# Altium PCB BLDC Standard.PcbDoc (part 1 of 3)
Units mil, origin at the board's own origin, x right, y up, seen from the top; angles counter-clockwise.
Board outline 4950 x 3000 mil, 4 copper layers (Top Layer, MidLayer1, MidLayer2, Bottom Layer), stack 63.4 mil thick; 211 components, 117 nets, 576 pads, 1027 vias.
Unrouted connection lines stored in the file: 2.
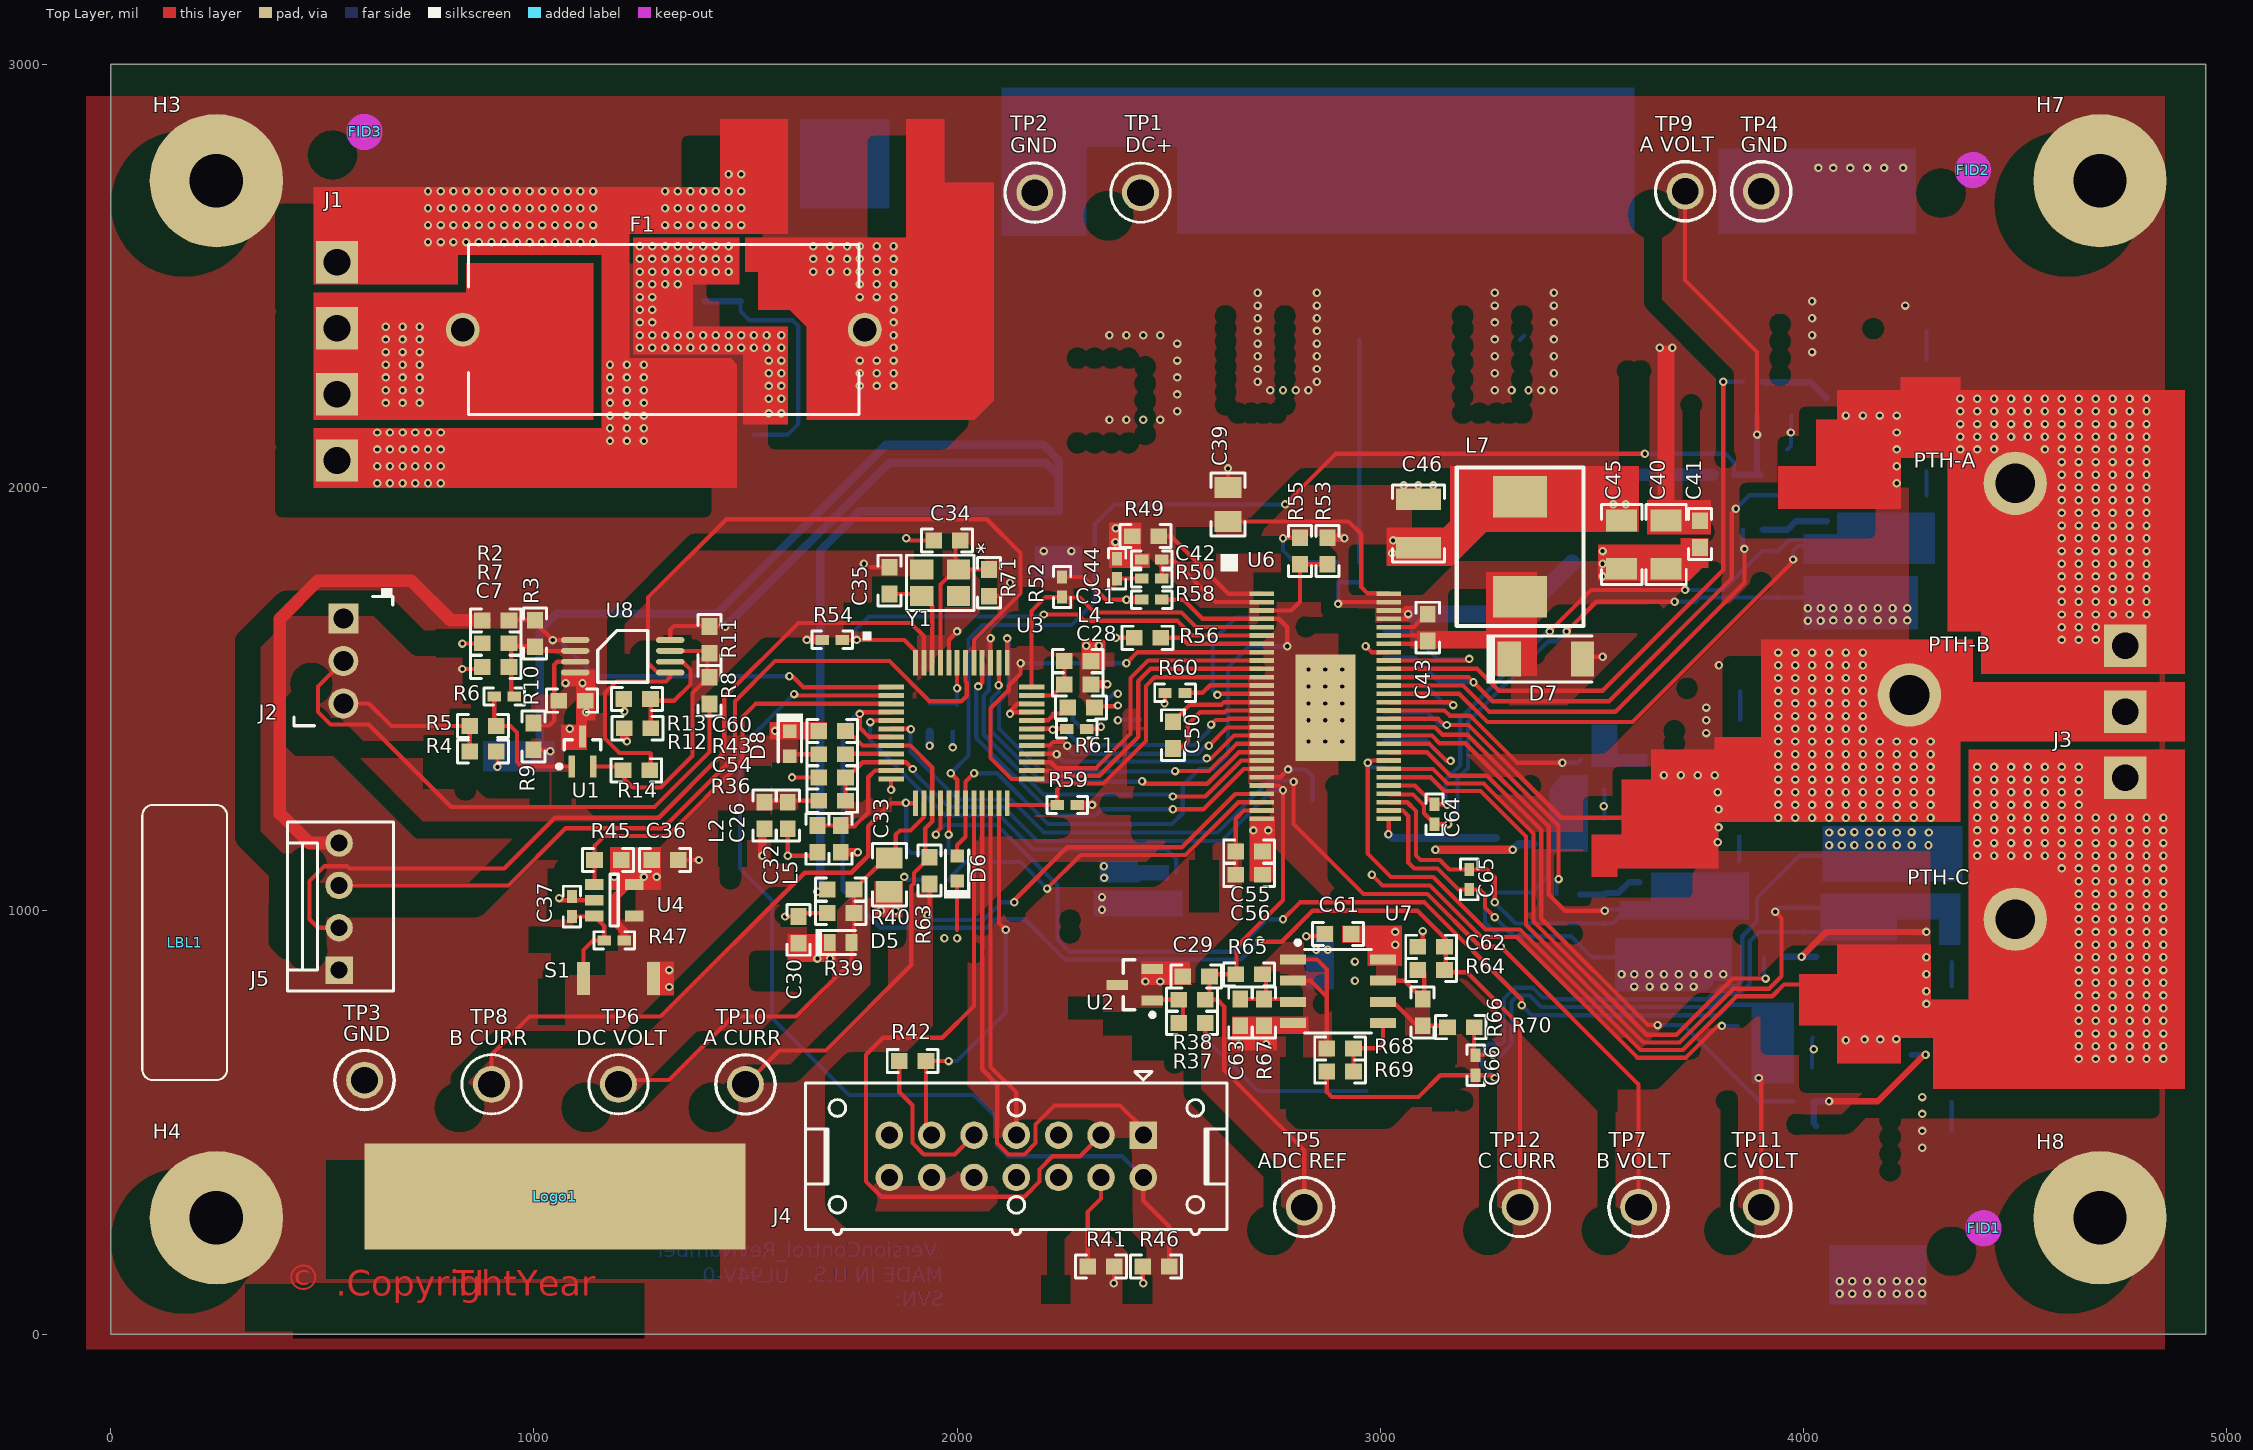
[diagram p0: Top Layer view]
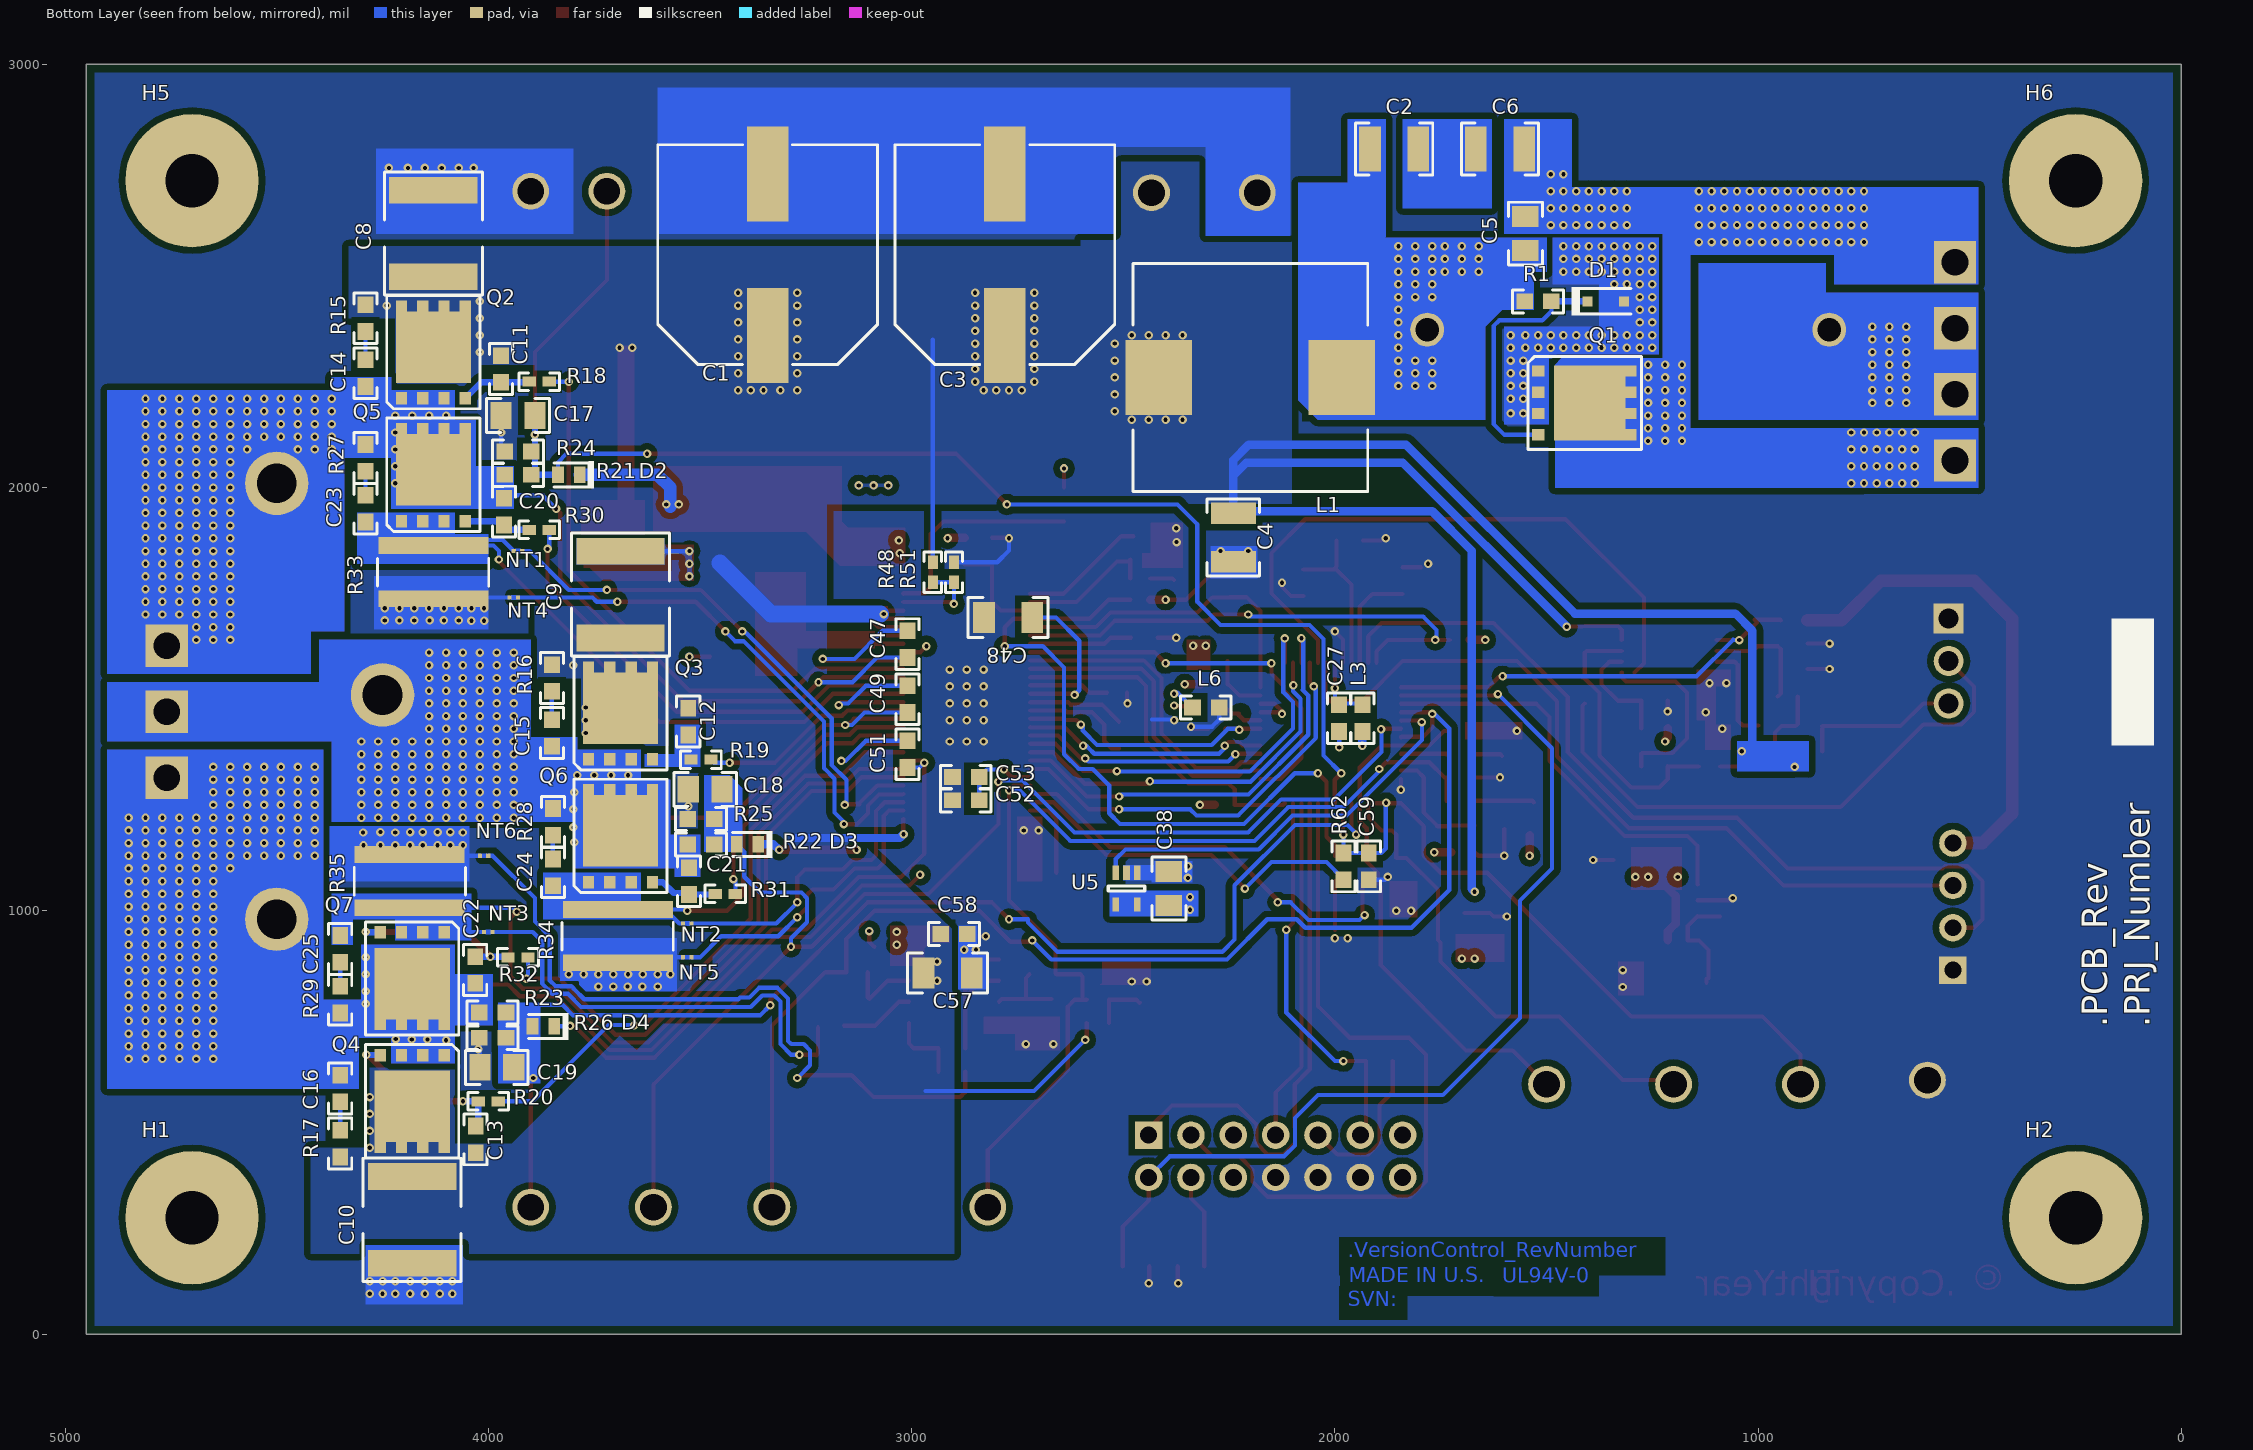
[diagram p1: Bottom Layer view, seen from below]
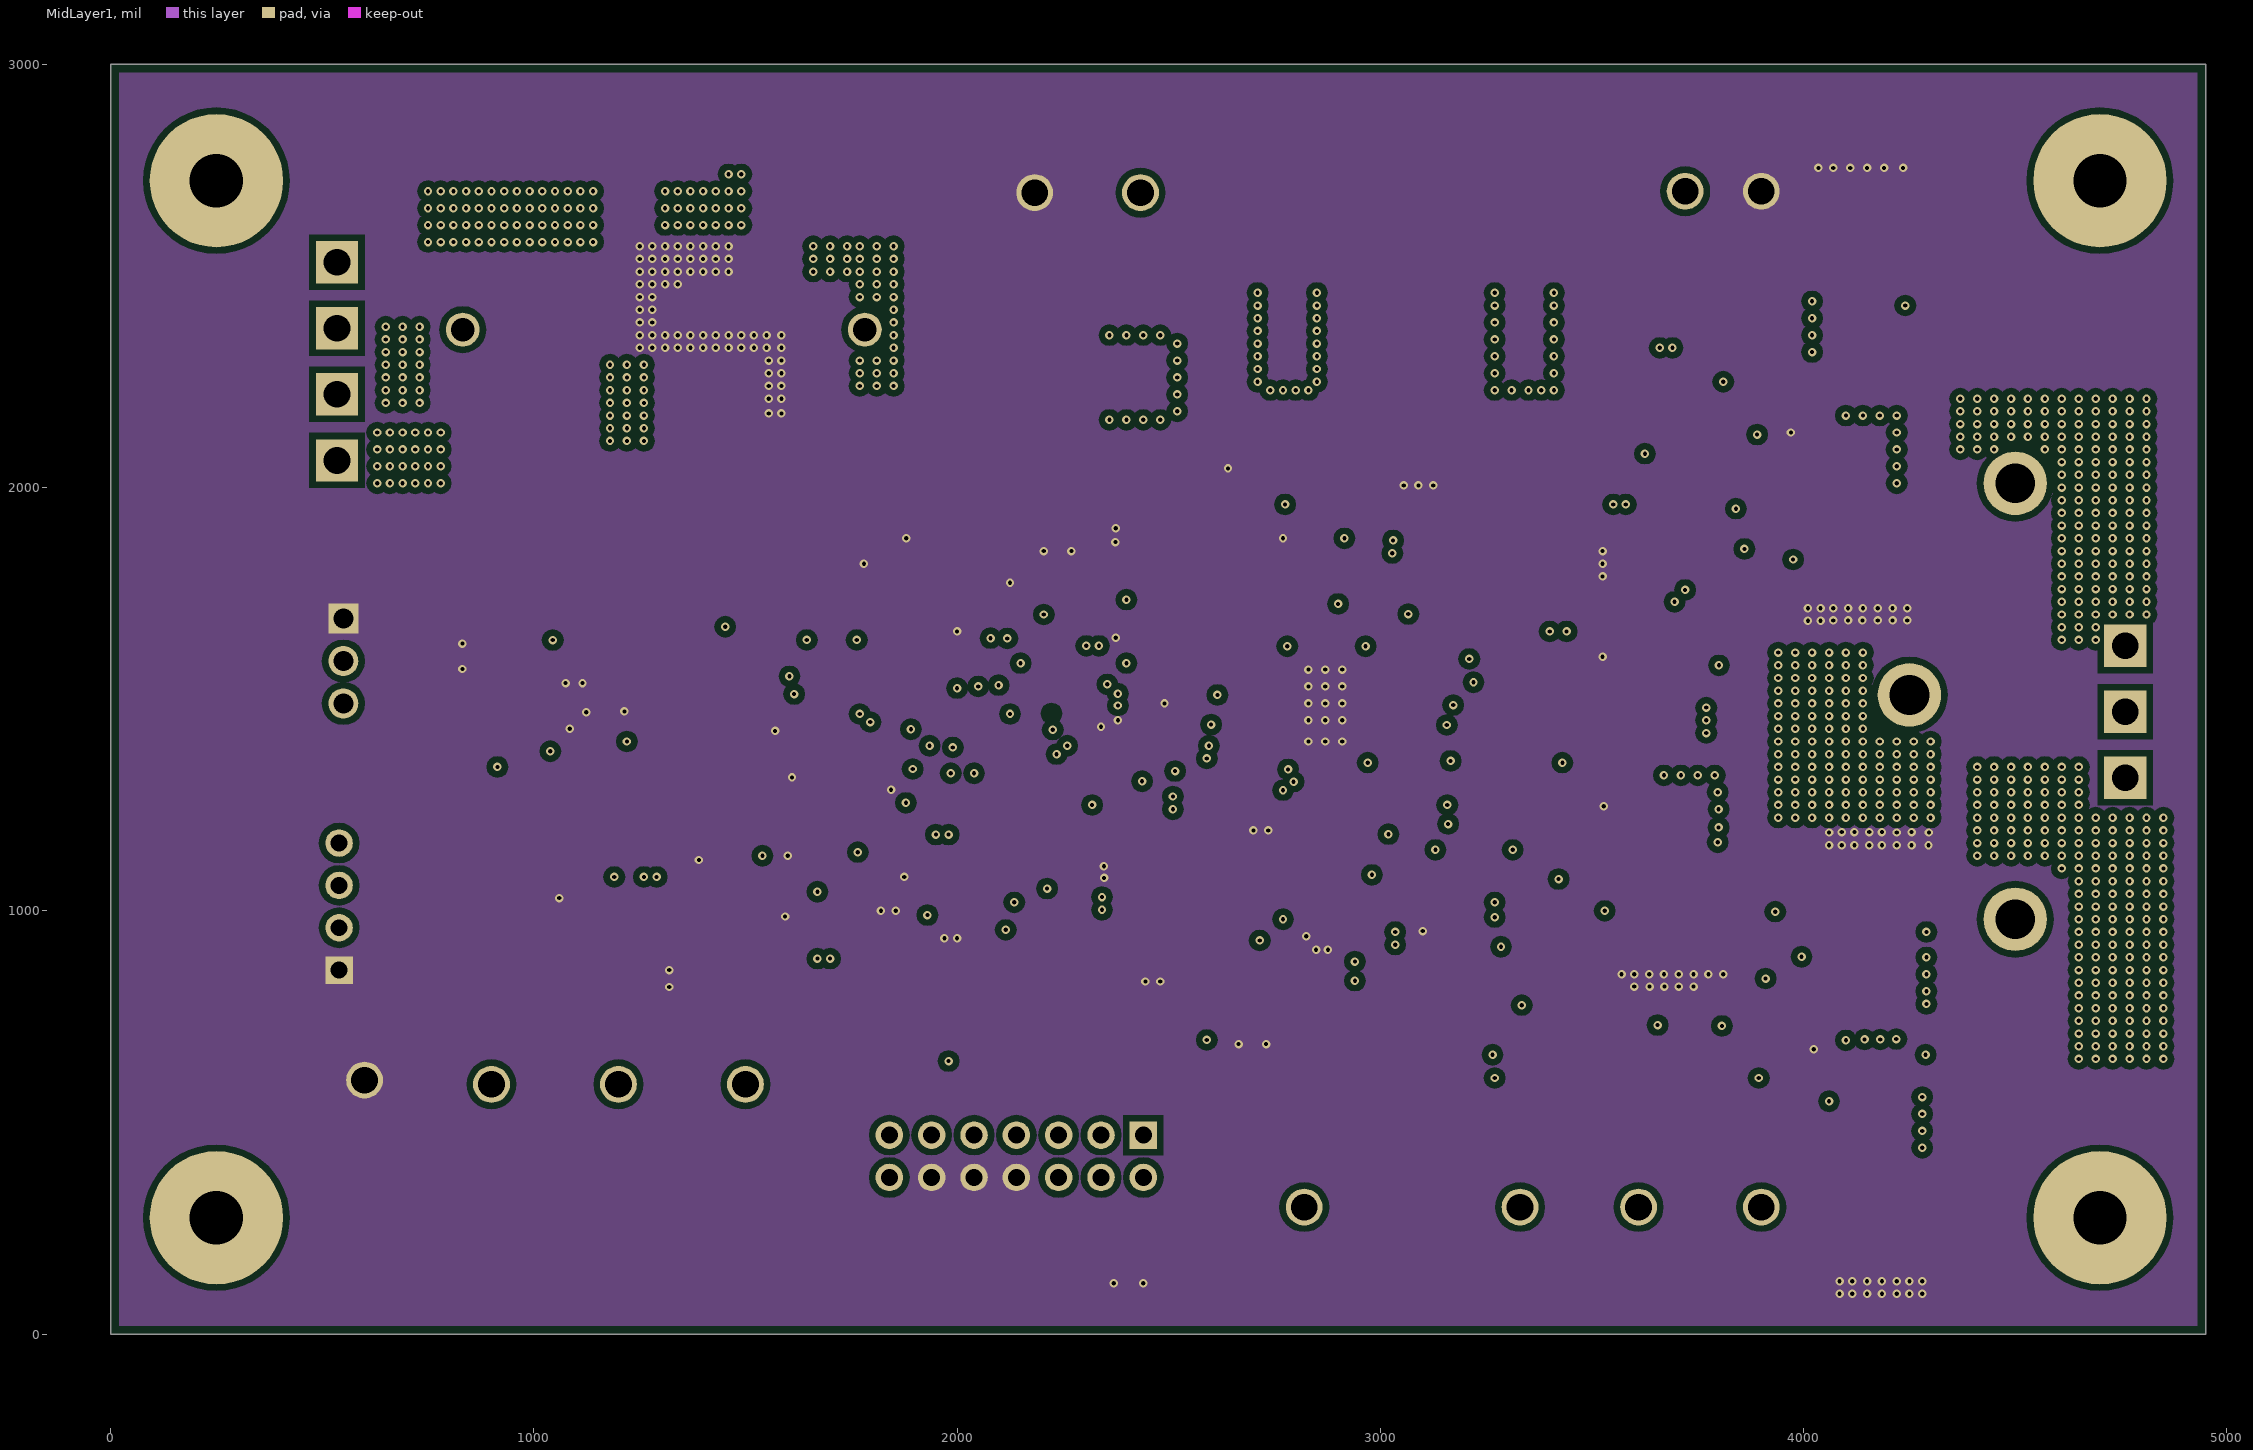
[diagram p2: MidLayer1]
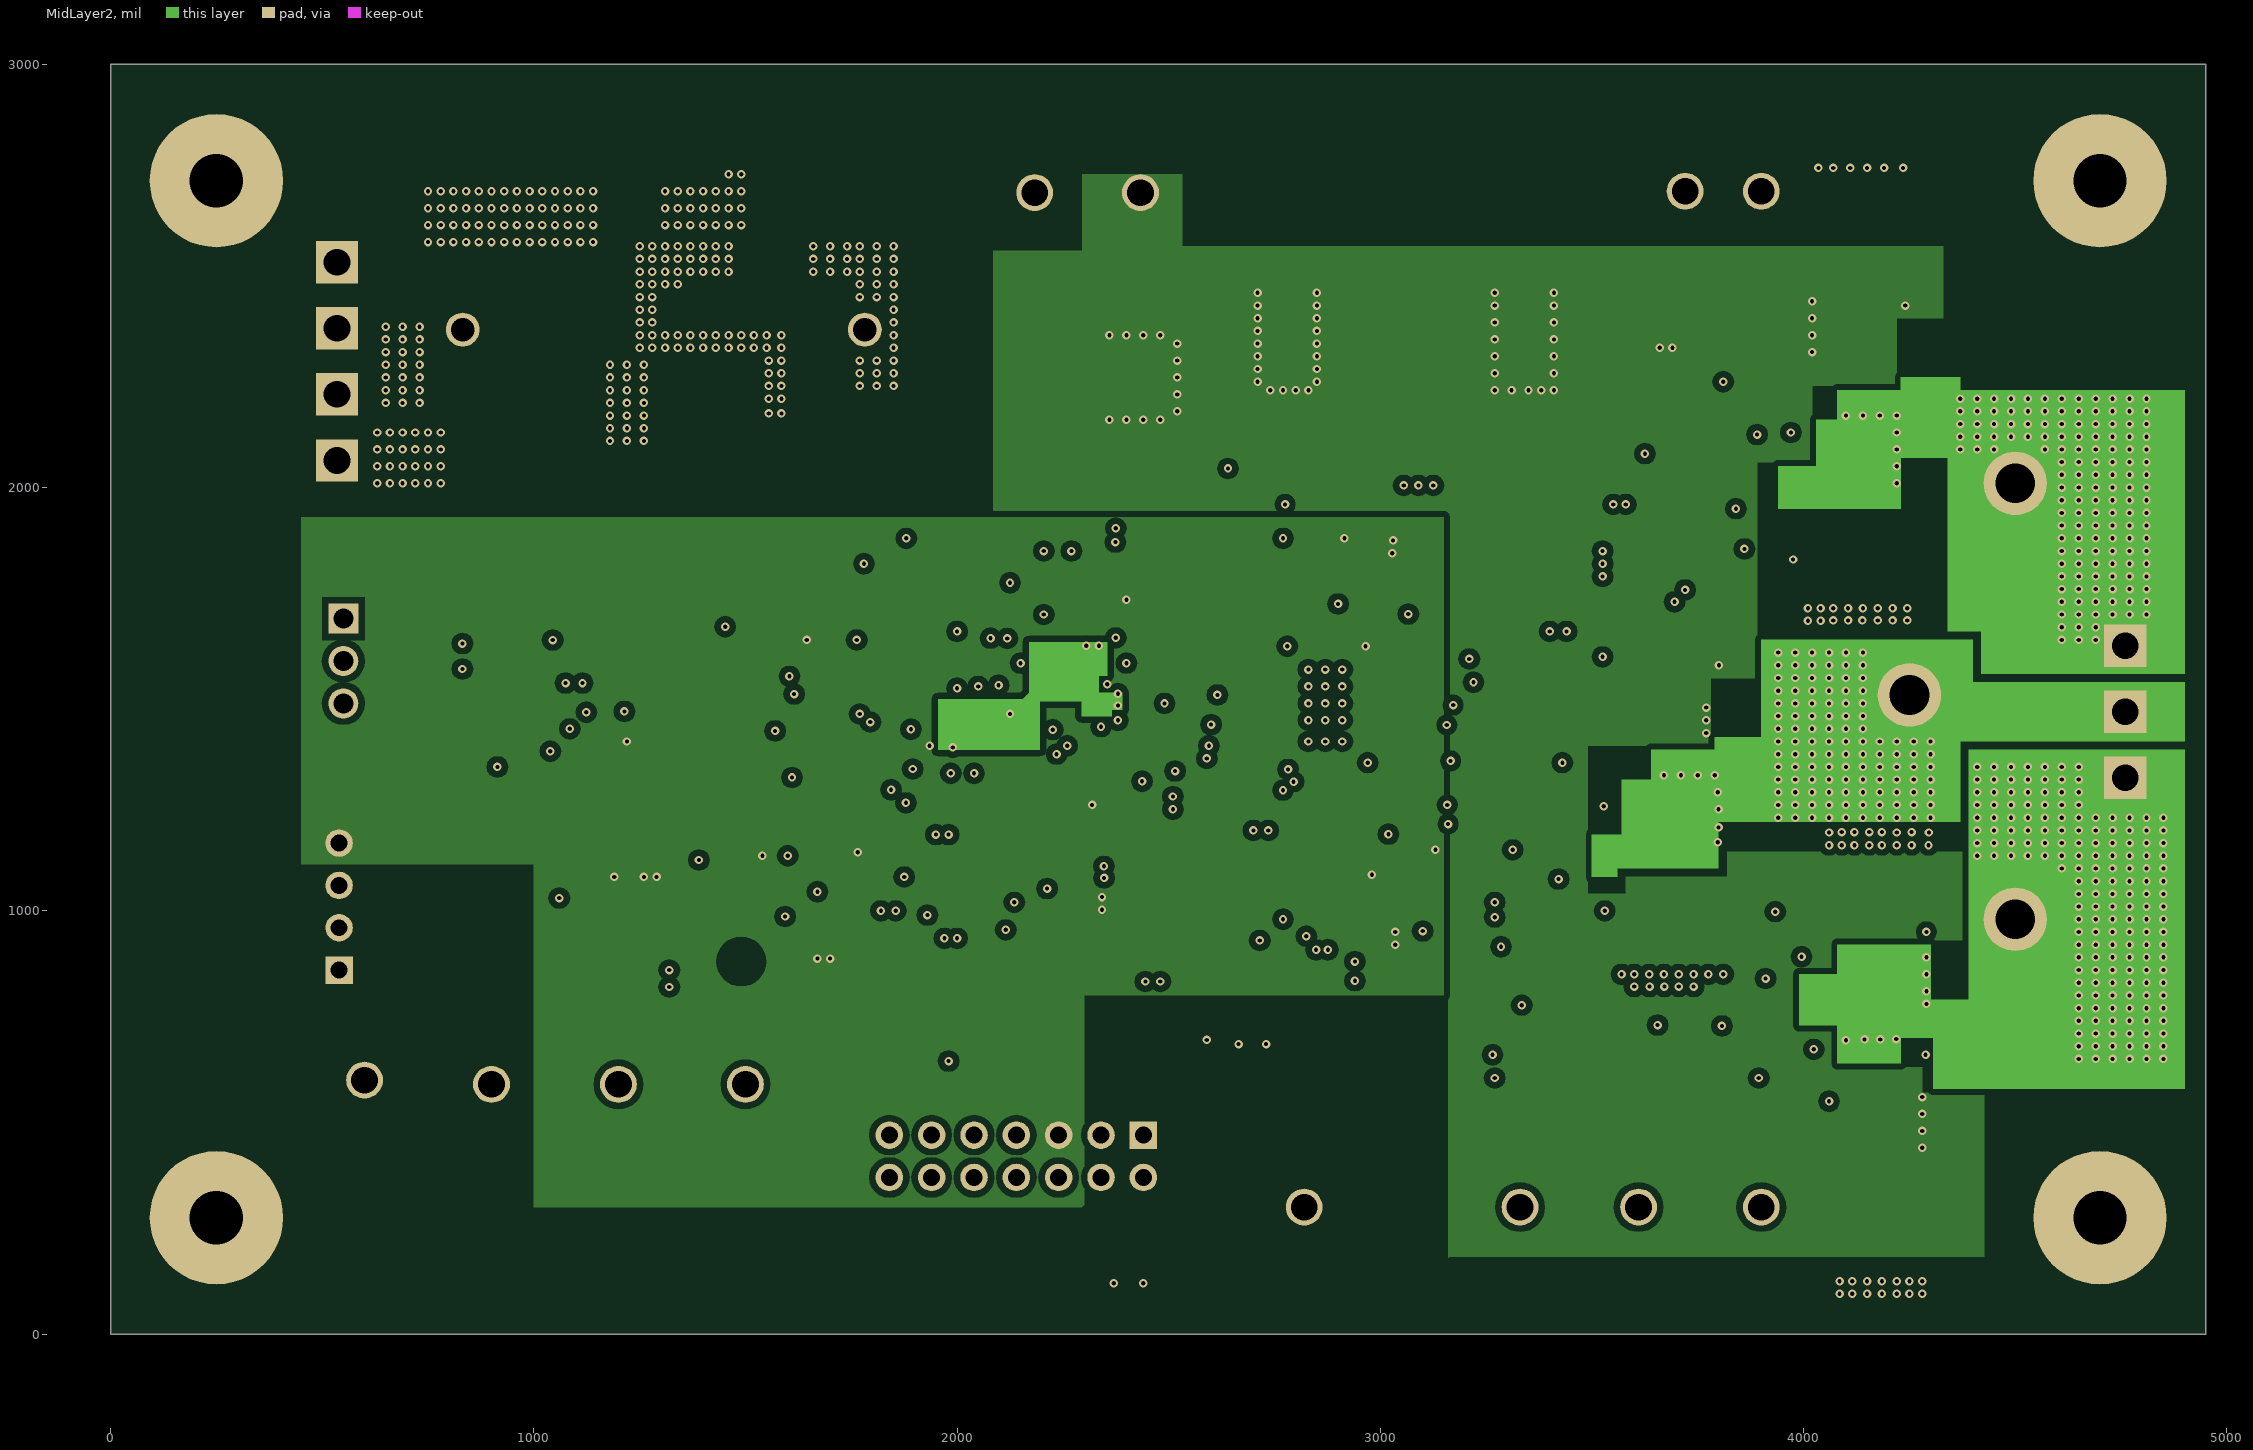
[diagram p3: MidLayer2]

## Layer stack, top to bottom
Top Layer: signal copper 1.4
Dielectric: prepreg 12.6, 370HR, Dk 4.8
MidLayer1: signal copper 1.4
Dielectric: core 32.6, 370HR, Dk 4.8
MidLayer2: signal copper 1.4
Dielectric: prepreg 12.6, 370HR, Dk 4.8
Bottom Layer: signal copper 1.4

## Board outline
0,0 4950,0 4950,3000 0,3000

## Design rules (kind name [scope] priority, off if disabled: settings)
AcuteAngle [All] p1: minimum=4.50000000000000E+0001 checktracksonly=FALSE
AssemblyTestPointUsage [All] p1: valid=2
Clearance Clearance_1 [InComponent('U3')] p1: gap=4
Clearance Clearance_BoardEdge_MountingHoles [OnCopper and InComponentClass('Mounting Holes') vs IsKeepOut] p2: gap=40
Clearance Clearance_BoardEdge_Poly [OnCopper and InPoly vs IsKeepOut] p3: gap=15
Clearance Clearance_BoardEdge [OnCopper and Not InComponentClass('Logo') and not InComponentClass('FiducialMark') and not InRegion(1000,500,4000,800) and Not IsKeepout vs IsKeepOut] p4: gap=75
Clearance Clearance_Poly [InPolygon] p5: gap=15
Clearance [All] p6: gap=8
ComponentClearance ComponentClearance_Logo [InComponentClass('Logo')] p1 off: gap=50 collisioncheckmode=3 verticalgap=10 showdistances=FALSE
ComponentClearance ComponentClearance_ScrewToNut [(HasFootprint('NY PMS 440 0025 PH')) vs (HasFootprint('Keystone_1902C'))] p2: gap=5 collisioncheckmode=3 verticalgap=10 showdistances=FALSE
ComponentClearance ComponentClearance_MountingHoles [InComponentClass('Mounting Holes')] p3 off: gap=250 collisioncheckmode=3 verticalgap=100000 showdistances=FALSE
ComponentClearance ComponentClearance_SmallPassives [HasFootprint('0201*') or HasFootprint('0402*') or HasFootprint('0508') or HasFootprint('0603*') or HasFootprint('0612') or HasFootprint('0805*') or HasFootprint('0815*') or HasFootprint('0830*') or HasFootprint('1206*') or HasFootprint('1210*') or HasFootprint('1808*') or HasFootprint('1812*') or HasFootprint('1825*') or HasFootprint('2010*') or HasFootprint('2220*') or HasFootprint('2225*') or HasFootprint('2512*') or HasFootprint('2728*') or HasFootprint('3518*') vs HasFootprint('0201*') or HasFootprint('0402*') or HasFootprint('0508') or HasFootprint('0603*') or HasFootprint('0612') or HasFootprint('0805*') or HasFootprint('0815*') or HasFootprint('0830*') or HasFootprint('1206*') or HasFootprint('1210*') or HasFootprint('1808*') or HasFootprint('1812*') or HasFootprint('1825*') or HasFootprint('2010*') or HasFootprint('2220*') or HasFootprint('2225*') or HasFootprint('2512*') or HasFootprint('2728*') or HasFootprint('3518*')] p4: gap=5 collisioncheckmode=3 verticalgap=10 showdistances=FALSE
ComponentClearance ComponentClearance_THtoSMT [IsThruComponent vs IsSMTComponent] p5: gap=20 collisioncheckmode=3 verticalgap=30 showdistances=FALSE
ComponentClearance ComponentClearance_THtoTH [IsThruComponent vs IsThruComponent] p6: gap=20 collisioncheckmode=3 verticalgap=30 showdistances=FALSE
ComponentClearance [All] p7 off: gap=40 collisioncheckmode=3 verticalgap=10 showdistances=FALSE
DiffPairsRouting [All] p1: maxlimit=100 minlimit=10 mostfreqgap=10 maxuncoupledlength=1000
FabricationTestPointUsage TestPointUsage [All] p1: valid=2 allowmultiple=FALSE
FabricationTestpoint Testpoint [All] p1: side=3 testpointundercomponent=TRUE minsize=40 maxsize=100 preferedsize=60 minholesize=0 maxholesize=40 preferedholesize=32 testpointgrid=1 allowsidetop=TRUE allowsidebottom=TRUE usegrid=TRUE gridtolerance=0.01
FanoutControl Fanout_LCC [IsLCC] p1: bgadir=Out bgaviamode=Centered fanoutstyle=Auto fanoutdirection=Alternating viagrid=1 // Fanout_LCC (Default Rule)
FanoutControl Fanout_BGA [IsBGA] p2: bgadir=Out bgaviamode=Centered fanoutstyle=Auto fanoutdirection=Alternating viagrid=1 // Fanout_BGA (Default Rule)
FanoutControl Fanout_Default [All] p4: bgadir=Out bgaviamode=Centered fanoutstyle=Auto fanoutdirection=Alternating viagrid=1 // Fanout_Default (Default Rule)
FanoutControl Fanout_Small [(CompPinCount < 5)] p5: bgadir=Out bgaviamode=Centered fanoutstyle=Auto fanoutdirection=OutThenIn viagrid=1 // Fanout_Small (Default Rule)
HoleSize [All] p1: absolutevalues=TRUE maxlimit=251 minlimit=8 maxpercent=80.000 minpercent=20.000
MinimumAnnularRing MinimumAnnularRing_ThermalPadVias [IsVia and InAnyComponent] p1: minimumring=5
MinimumAnnularRing [All] p2: minimumring=5
MinimumSolderMaskSliver MinimumSolderMaskSliver_Logo [InComponentClass('Logo') vs InComponentClass('Logo')] p1: minsoldermaskwidth=0.7
MinimumSolderMaskSliver [All] p2: minsoldermaskwidth=2.5
PlaneClearance [All] p1: clearance=5
PlaneConnect [All] p1: planeconnectstyle=Direct reliefexpansion=10 reliefentries=4 reliefconductorwidth=10 reliefairgap=10
PolygonConnect [All] p1: connectstyle=Direct reliefconductorwidth=10 reliefentries=4 polygonreliefangle="90 Angle" airgapwidth=10
RoomDefinition Hardware_ANSI-B [InComponentClass('Hardware_ANSI-B')] p1: confinementstyle=ConfineIn formatcopy=TRUE lockcomponents=FALSE outline -692,-1534 1308,-1534 1308,-534 -692,-534
RoomDefinition "BLDC Standard sheet 4" [InComponentClass('BLDC Standard sheet 4')] p2: confinementstyle=ConfineIn formatcopy=TRUE lockcomponents=FALSE outline -692,-1534 1308,-1534 1308,-534 -692,-534
RoomDefinition "BLDC Standard sheet 3" [InComponentClass('BLDC Standard sheet 3')] p3: confinementstyle=ConfineIn formatcopy=TRUE lockcomponents=FALSE outline -692,-1534 1308,-1534 1308,-534 -692,-534
RoomDefinition "BLDC Standard sheet 2" [InComponentClass('BLDC Standard sheet 2')] p4: confinementstyle=ConfineIn formatcopy=TRUE lockcomponents=FALSE outline -692,-1534 1308,-1534 1308,-534 -692,-534
RoomDefinition "BLDC Standard sheet 1" [InComponentClass('BLDC Standard sheet 1')] p5: confinementstyle=ConfineIn formatcopy=TRUE lockcomponents=FALSE outline -692,-1534 1308,-1534 1308,-534 -692,-534
RoutingVias ThermalPadVias [IsVia and InAnyComponent] p1: holewidth=7.87 width=19.68 viastyle="Through Hole" minholewidth=7.87 minwidth=19.68 maxholewidth=12.99 maxwidth=23.62
RoutingVias [All] p2: holewidth=16 width=34 viastyle="Through Hole" minholewidth=7.87 minwidth=20 maxholewidth=40 maxwidth=65
SMDToCorner [All] p1: distance=30000
SilkToSilkClearance [All] p1: silktosilkclearance=3
SilkscreenOverComponentPads [All] p1: minsilkscreentomaskgap=3
SolderMaskExpansion [All] p1: expansion=1.97
Width [All] p1: maxlimit=100 minlimit=6 preferedwidth=10 checkconnectedcopper=TRUE
13 further rules are at their usual default settings.

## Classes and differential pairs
component class "BLDC Standard sheet 4": C8 C9 C10 C11 C12 C13 C14 C15 C16 C17 C18 C19 C20 C21 C22 C23 C24 C25 D2 D3 D4 J3 NT1 NT2 NT3 NT4 NT5 NT6 PTH-A PTH-B PTH-C Q2 Q3 Q4 Q5 Q6 Q7 R15 R16 R17 R18 R19 R20 R21 R22 R23 R24 R25 R26 R27 R28 R29 R30 R31 R32 R33 R34 R35
component class "BLDC Standard sheet 3": C39 C40 C41 C42 C43 C44 C45 C46 C47 C48 C49 C50 C51 C52 C53 C54 C55 C56 C57 C58 C59 C60 C61 C62 C63 C64 C65 C66 D6 D7 L7 R48 R49 R50 R51 R52 R53 R54 R55 R56 R58 R59 R60 R61 R62 R63 R64 R65 R66 R67 R68 R69 R70 U6 U7
component class "BLDC Standard sheet 2": C26 C27 C28 C29 C30 C31 C32 C33 C34 C35 C36 C37 C38 D5 D8 HD1 J4 J5 L2 L3 L4 L5 L6 R36 R37 R38 R39 R40 R41 R42 R43 R45 R46 R47 R71 S1 TP5 TP6 TP7 TP8 TP9 TP10 TP11 TP12 U2 U3 U4 U5 Y1
component class "BLDC Standard sheet 1": C1 C2 C3 C4 C5 C6 C7 D1 F1 J1 J2 L1 Q1 R1 R2 R3 R4 R5 R6 R7 R8 R9 R10 R11 R12 R13 R14 TP1 TP2 TP3 TP4 U1 U8
component class AssemblyNote: ZZ1 ZZ2 ZZ3 ZZ4
component class FiducialMark: FID1 FID2 FID3
component class Hardware_ANSI-B: !PCB1 FID1 FID2 FID3 H1 H2 H3 H4 H5 H6 H7 H8 LBL1 Logo1 ZZ1 ZZ2 ZZ3 ZZ4
component class Label: LBL1
component class Logo: Logo1
component class "Mounting Holes": H3 H4 H7 H8

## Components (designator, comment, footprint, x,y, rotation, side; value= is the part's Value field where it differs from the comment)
C1 "EMVH500ARA221MKE0S" CAPSMT_62_KE0 3340,2550 r90 bottom
C2 "GRM32ER71H106KA12L" 1210 1860,2800 r180 bottom
C3 "EMVH500ARA221MKE0S" CAPSMT_62_KE0 2780,2550 r90 bottom
C4 "GRM32ER71H106KA12L" 1210 2240,1882 r270 bottom
C5 "08055A681JAT2A" 0805_HV 1550,2600 r90 bottom
C6 "GRM32ER71H106KA12L" 1210 1610,2800 r180 bottom
C7 "06031C103JAT2A" 0603 910,1576 r180 top
C8 "C5750X7R2A475M" 2220 4130,2600 r90 bottom
C9 "C5750X7R2A475M" 2220 3687.8,1746.97 r90 bottom
C10 "C5750X7R2A475M" 2220 4180,270 r270 bottom
C11 "06035A220JAT2A" 0603 3970,2280 r270 bottom
C12 "06035A220JAT2A" 0603 3527.8,1446.97 r270 bottom
C13 "06035A220JAT2A" 0603 4030,460 r90 bottom
C14 "C1608X7R1H473K" 0603 4290,2270 r270 bottom
C15 "C1608X7R1H473K" 0603 3850,1420 r270 bottom
C16 "C1608X7R1H473K" 0603 4350,580 r90 bottom
C17 "C0805C104K4RACTU" 0805_HV 3930,2170 r0 bottom
C18 "C0805C104K4RACTU" 0805_HV 3487.8,1286.97 r0 bottom
C19 "C0805C104K4RACTU" 0805_HV 3980,630 r0 bottom
C20 "06035A220JAT2A" 0603 3963,1943 r270 bottom
C21 "06035A220JAT2A" 0603 3526,1070 r270 bottom
C22 "06035A220JAT2A" 0603 4031,860 r90 bottom
C23 "C1608X7R1H473K" 0603 4290,1950 r270 bottom
C24 "C1608X7R1H473K" 0603 3847,1091 r270 bottom
C25 "C1608X7R1H473K" 0603 4350,910 r90 bottom
C26 "GRM188R60J106ME47D" 0603 1600,1225 r270 top
C27 "GRM188R60J106ME47D" 0603 1990,1455 r270 bottom
C28 "GRM188R71A225KE15D" 0603 2293,1480 r0 top
C29 "C1608X7R1C105K" 0603 2565,845 r180 top
C30 "GRM188R60J106ME47D" 0603 1625,955 r270 top
C31 "GRM188R60J106ME47D" 0603 2285,1590 r0 top
C32 "GRM188R60J106ME47D" 0603 1670,1170 r270 top
C33 "C0805C104K4RACTU" 0805_HV 1840,1085 r270 top
C34 "06035A120JAT2A" 0603 1976.1,1875 r180 top
C35 "06035A120JAT2A" 0603 1840,1780 r90 top
C36 "GCM188R71H104KA57B" 0603 1310,1120 r0 top
C37 "UMK105B7222KV-F" 0402 1090,1010 r90 top
C38 "C0805C104K4RACTU" 0805_HV 2392.32,1052.56 r90 bottom
C39 "08055C103JAT2A" 0805_HV 2640,1960 r270 top
C40 "GRM31CR71H475KA12L" 1206 3675,1865 r270 top
C41 "06035C104KAT2A" 0603 3755,1890 r270 top
C42 "GRM1555C1H750JA01D" 0402 2460,1830 r180 top
C43 "06035C104KAT2A" 0603 3112,1669 r90 top
C44 "GRM155R61A393KA01D" 0402 2378,1808 r90 top
C45 "GRM31CR71H475KA12L" 1206 3570,1865 r270 top
C46 "GRM32ER71A476KE15L" 1210 3090,1915 r90 top
C47 "06035C104KAT2A" 0603 3010,1630 r270 bottom
C48 "GRM31MR71A225KA01L" 1206 2772,1693 r0 bottom
C49 "06035C104KAT2A" 0603 3010,1500 r270 bottom
C50 "C0603C223K5RACTU" 0603 2510,1415 r270 top
C51 "06035C104KAT2A" 0603 3010,1370 r270 bottom
C52 "06035C104KAT2A" 0603 2872,1261 r0 bottom
C53 "C1608X7R1C105K" 0603 2872,1316 r0 bottom
C54 "06035C104KAT2A" 0603 1705,1315 r180 top
C55 "06035C104KAT2A" 0603 2690,1140 r0 top
C56 "C1608X7R1C105K" 0603 2690,1085 r0 top
C57 "GRM31MR71A225KA01L" 1206 2915,853 r180 bottom
C58 "06035C104KAT2A" 0603 2900,945 r180 bottom
C59 "GRM188R71C273KA01D" 0603 1920,1105 r270 bottom
C60 "GRM188R71C273KA01D" 0603 1705,1425 r180 top
C61 "06035C104KAT2A" 0603 2900,945 r0 top
C62 "GRM188R71C273KA01D" 0603 3120,915 r180 top
C63 "06035C104KAT2A" 0603 2669,760 r270 top
C64 "GRM155R71H102KA01D" 0402 3128,1228 r270 top
C65 "GRM155R71H102KA01D" 0402 3210,1074.08 r270 top
C66 "GRM155R71H102KA01D" 0402 3225,635 r90 top
D1 "MMSZ5245BS-7-F" sod-323 1360,2440 r180 bottom
D2 "CD0603-B0130L" Diode_0603 3810,2030 r0 bottom
D3 "CD0603-B0130L" Diode_0603 3387.8,1156.97 r0 bottom
D4 "CD0603-B0130L" Diode_0603 3870,727 r0 bottom
D5 "CD0603-B0130L" Diode_0603 1725,925 r0 top
D6 "LTST-C190GKT" LED_LTST-C190 2000,1100 r270 top
D7 "CMS06" M-FLAT 3391,1595 r0 top
D8 "LTST-C190KFKT" LED_LTST-C190 1605,1395 r90 top
F1 "05200101Z" 05200101Z 1307,2373 r0 top
FID1 "Fiducial" Fiducial10-20 4425,250 r90 top
FID2 "Fiducial" Fiducial10-20 4400,2750 r90 top
FID3 "Fiducial" Fiducial10-20 600,2840 r90 top
H1 "1902C" Keystone_1902C 4699.99,274.77 r90 bottom
H2 "1902C" Keystone_1902C 249.99,274.77 r90 bottom
H3 "NY PMS 440 0025 PH" "NY PMS 440 0025 PH" 250,2725 r90 top
H4 "NY PMS 440 0025 PH" "NY PMS 440 0025 PH" 250,275 r90 top
H5 "1902C" Keystone_1902C 4700,2725 r90 bottom
H6 "1902C" Keystone_1902C 249.99,2724.77 r90 bottom
H7 "NY PMS 440 0025 PH" "NY PMS 440 0025 PH" 4700,2725 r90 top
H8 "NY PMS 440 0025 PH" "NY PMS 440 0025 PH" 4700,275 r90 top
J1 "CONN_1-1318300-4" CONN_1-1318300-4 535,2220 r90 top
J2 "22-27-2031" MOLEX_22-27-2031 550,1590 r270 top
J3 "CONN_1-1318300-3" CONN_1-1318300-3 4760,1470 r270 top
J4 "SBH11-PBPC-D07-ST-BK" CONN_SBH11-PBPC-D07-ST-BK 2140,420 r180 top
J5 "0022112042" CONN_22112042 540,1010 r90 top
L1 "SRP1250-4R7M" SRP1250-4R7MTR 2200,2260 r0 bottom
L2 "BLM18SG121TN1D" 0603 1545,1225 r90 top
L3 "DO NOT INSTALL" 0603 1935,1455 r90 bottom
L4 "BLM18SG121TN1D" 0603 2285,1535 r180 top
L5 "BLM18SG121TN1D" 0603 1725,1170 r90 top
L6 "BLM18SG121TN1D" 0603 2305,1480 r0 bottom
L7 "DR74-101-R" DR74 3330,1860 r90 top
LBL1 "Size: 0.65\" x 0.20 \"" Label_650x200 175,925 r90 top
Logo1 "Texas Instruments" TI_Stacked_SolderMask_Small 1050,325 r0 top
NT1 "Net-Tie" Net-Tie_10mil 3930,1850 r180 bottom net-tie
NT2 "Net-Tie" Net-Tie_10mil 3530,970 r180 bottom net-tie
NT3 "Net-Tie" Net-Tie_10mil 4000,950 r180 bottom net-tie
NT4 "Net-Tie" Net-Tie_10mil 3940,1740 r180 bottom net-tie
NT5 "Net-Tie" Net-Tie_10mil 3530,890 r180 bottom net-tie
NT6 "Net-Tie" Net-Tie_10mil 4010,1130 r180 bottom net-tie
PTH-A "TH-094MIL" TH-094MIL 4500,2010 r90 top
PTH-B "TH-094MIL" TH-094MIL 4250,1510 r90 top
PTH-C "TH-094MIL" TH-094MIL 4500,980 r90 top
Q1 "CSD18501Q5A" TRANS_NexFET_Q5A 1410,2200 r180 bottom
Q2 "CSD18501Q5A" TRANS_NexFET_Q5A 4130,2320 r90 bottom
Q3 "CSD18501Q5A" TRANS_NexFET_Q5A 3687.8,1466.97 r90 bottom
Q4 "CSD18501Q5A" TRANS_NexFET_Q5A 4180,550 r270 bottom
Q5 "CSD18501Q5A" TRANS_NexFET_Q5A 4130,2030 r90 bottom
Q6 "CSD18501Q5A" TRANS_NexFET_Q5A 3687.8,1176.97 r90 bottom
Q7 "CSD18501Q5A" TRANS_NexFET_Q5A 4180,840 r270 bottom
R1 "CRCW060352K3FKEA" 0603 1520,2440 r0 bottom
R2 "CRCW060310K0JNEA" 0603 910,1686 r180 top
R3 "ERJ-3GEY0R00V" 0603 1003,1655 r90 top
R4 "CRCW060310K0JNEA" 0603 880,1376.3 r0 top
R5 "CRCW06031K50JNEA" 0603 880,1436.3 r0 top
R6 "CRCW040210K0JNED" 0402 930,1506.3 r180 top
R7 "CRCW06032K70JNEA" 0603 910,1632 r0 top
R8 "CRCW06031K50JNEA" 0603 1415,1520 r90 top
R9 "CRCW060320K0JNEA" 0603 999,1412 r270 top
R10 "CRCW06032K70JNEA" 0603 1090,1496.3 r0 top
R11 "CRCW060310K0JNEA" 0603 1415,1640 r90 top
R12 "CRCW060310K0JNEA" 0603 1245,1431.3 r180 top
R13 "CRCW060310K0JNEA" 0603 1244,1500 r0 top
R14 "ERJ-3GEY0R00V" 0603 1242,1332 r180 top
R15 "CRCW06032R21FKEA" 0603 4290,2400 r270 bottom
R16 "CRCW06032R21FKEA" 0603 3850,1550 r270 bottom
R17 "CRCW06032R21FKEA" 0603 4350,450 r90 bottom
R18 "CRCW04021R00FKED" 0402 3880,2250 r0 bottom
R19 "CRCW04021R00FKED" 0402 3497.8,1356.97 r0 bottom
R20 "CRCW04021R00FKED" 0402 4000,550 r0 bottom
R21 "CRCW060334K8FKEA" 0603 3930,2030 r180 bottom
R22 "CRCW060334K8FKEA" 0603 3497.8,1156.97 r180 bottom
R23 "CRCW060334K8FKEA" 0603 3990,760 r180 bottom
R24 "CRCW06034K99FKEA" 0603 3930,2085 r180 bottom
R25 "CRCW06034K99FKEA" 0603 3497.8,1216.97 r180 bottom
R26 "CRCW06034K99FKEA" 0603 3990,700 r180 bottom
R27 "CRCW06032R21FKEA" 0603 4290,2070 r270 bottom
R28 "CRCW06032R21FKEA" 0603 3847,1210 r270 bottom
R29 "CRCW06032R21FKEA" 0603 4350,790 r90 bottom
R30 "CRCW04021R00FKED" 0402 3880,1900 r0 bottom
R31 "CRCW04021R00FKED" 0402 3440,1040 r0 bottom
R32 "CRCW04021R00FKED" 0402 3930,890 r0 bottom
R33 "FCSL64R010FER" 2512_WIDE 4130,1800 r90 bottom
R34 "FCSL64R010FER" 2512_WIDE 3694,940 r90 bottom
R35 "FCSL64R010FER" 2512_WIDE 4186,1070 r270 bottom
R36 "ERJ-3GEY0R00V" 0603 1705,1260 r0 top
R37 "CRCW060331K6FKEA" 0603 2555,735 r0 top
R38 "ERJ-3GEY0R00V" 0603 2555,790 r0 top
R39 "CRCW060334K8FKEA" 0603 1725,1050 r0 top
R40 "CRCW06034K99FKEA" 0603 1725,995 r0 top
R41 "ERJ-3GEY0R00V" 0603 2340,160 r180 top
R42 "ERJ-3GEY0R00V" 0603 1895,645 r0 top
R43 "CRCW06031K00JNEA" 0603 1705,1370 r180 top
R45 "CRCW06032K20JNEA" 0603 1175,1120 r0 top
R46 "CRCW06032K20JNEA" 0603 2470,160 r0 top
R47 "CRCW040247K0JNED" 0402 1190,930 r0 top
R48 "CRCW0402300KJNED" 0402 2950,1800 r90 bottom
R49 "CRCW0603249KFKEA" 0603 2445,1885 r0 top
R50 "CRCW04028K87FKED" 0402 2460,1785 r0 top
R51 "CRCW040275K0JNED" 0402 2900,1800 r270 bottom
R52 "CRCW040210K0JNED" 0402 2248,1765 r270 top
R53 "CRCW060331K6FKEA" 0603 2875,1850 r90 top
R54 "CRCW040210K0JNED" 0402 1705,1640 r0 top
R55 "CRCW060310K0FKEA" 0603 2810,1850 r270 top
R56 "CRCW06031K00JNEA" 0603 2450,1645 r0 top
R58 "CRCW04021K00JNED" 0402 2460,1735 r180 top
R59 "CRCW040210K0JNED" 0402 2260,1250 r180 top
R60 "CRCW040210K0JNED" 0402 2515,1515 r0 top
R61 "CRCW040210K0JNED" 0402 2283,1429 r180 top
R62 "CRCW060356R2FKEA" 0603 1980,1105 r90 bottom
R63 "CRCW060356R2FKEA" 0603 1935,1095 r90 top
R64 "CRCW060356R2FKEA" 0603 3120,860 r0 top
R65 "CRCW060310K0FKEA" 0603 2690,850 r180 top
R66 "CRCW060320K0FKEA" 0603 3100,760 r90 top
R67 "CRCW060310K0FKEA" 0603 2725,760 r270 top
R68 "CRCW060320K0FKEA" 0603 2905,675 r180 top
R69 "CRCW06031K00JNEA" 0603 2905,620 r0 top
R70 "CRCW06031K00JNEA" 0603 3190,725 r180 top
R71 "ERJ-3GEY0R00V" 0603 2075,1775 r270 top
S1 "SKRKAEE010" SW_SKRKAEE010 1200,840 r180 top
TP1 "5125" Keystone5125 2433.31,2696.69 r0 top
TP2 "5011" Keystone5011 2183.31,2696.69 r0 top
TP3 "5011" Keystone5011 600,600 r0 top
TP4 "5011" Keystone5011 3900,2700 r0 top
TP5 "5012" Keystone5012 2820,300 r0 top
TP6 "5128" Keystone5128 1200,590 r0 top
TP7 "5014" Keystone5014 3610,300 r0 top
TP8 "5126" Keystone5126 900,590 r0 top
TP9 "5010" Keystone5010 3720,2700 r0 top
TP10 "5013" Keystone5013 1500,590 r0 top
TP11 "5127" Keystone5127 3900,300 r0 top
TP12 "5129" Keystone5129 3330,300 r0 top
U1 "TPD2E007DCKR" DCK0003A_N 1115,1376.3 r90 top
U2 "LM4040DEM3-3.0" MF03A_N 2420,825 r180 top
U3 "TMS320F28027FPTQ" PT-48 2010,1420 r270 top
U4 "TPS3828-33DBV" DBV0005A_N 1190,1025 r0 top
U5 "LMT86DCKT" DCK0005A_N 2492.32,1052.56 r270 bottom
U6 "DRV8301" DCA_56P 2870,1480 r0 top
U7 "OPA2365AQDRQ1" OPA2365AQDRQ1 2900,810 r270 top
U8 "LM2903VQPWRQ1" PW0008A_N 1210,1601.3 r0 top
Y1 "NX3225GA20MHZSTDCRA1" XTAL_NX3225SA 1960,1775 r180 top
ZZ1 "This Assembly Note is for PCB labels only" AssemblyNoteLabel 100,3925 r0 top
ZZ2 "These assemblies are ESD sensitive, ESD precautions shall be observed." AssemblyNote 100,3725 r0 top
ZZ3 "These assemblies must be clean and free from flux and all contaminants. Use of no clean flux is not acceptable." AssemblyNote 100,3525 r0 top
ZZ4 "These assemblies must comply with workmanship standards IPC-A-610 Class 2., unless otherwise specified." AssemblyNote 100,3325 r0 top

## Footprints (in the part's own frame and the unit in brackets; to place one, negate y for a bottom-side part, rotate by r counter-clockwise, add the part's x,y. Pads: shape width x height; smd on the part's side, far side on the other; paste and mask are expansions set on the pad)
0402 [mm] "0402 from SM-752 data"
  rect 0.8x0.6 smd: 1(-0.6,0) 2(0.6,0)
  silkscreen extent -1.22,-0.52 1.22,0.52, body extent -0.55,-0.3 0.55,0.3, height 0.6
0603 [mm] "0603 from SM-752 data"
  rect 1x0.95 smd: 1(-0.8,0) 2(0.8,0)
  silkscreen extent -1.52,-0.69 1.52,0.69, body extent -0.87,-0.47 0.87,0.47, height 0.85
0805_HV [mil] "0805 with 30mil clearance between pads"
  rect 50x63 smd: 1(-40,0) 2(40,0)
  silkscreen extent -74,-40 74,40, body extent -43,-29 43,29, height 43
1206 [mm] "1206 from SM-752 data"
  rect 1.3x1.85 smd: 1(-1.45,0) 2(1.45,0)
  silkscreen extent -2.4,-1.21 2.4,1.21, body extent -1.7,-0.9 1.7,0.9, height 1.35
1210 [mm] "1210 from SM-752 data"
  rect 1.3x2.7 smd: 1(-1.45,0) 2(1.45,0)
  silkscreen extent -2.32,-1.57 2.32,1.57, body extent -1.7,-1.35 1.7,1.35, height 1.35
2220 [mm] "Chip Capacitor, Body 5.7x5.0mm, IPC Medium Density"
  rect 1.6x5.3 smd: 1(-2.6,0) 2(2.6,0)
  silkscreen extent -3.69,-2.94 3.69,2.94, body extent -2.95,-2.62 2.95,2.62, height 1.35
2512_WIDE [mm] "Ohmite recommended land pattern"
  rect 1x6.6 smd: 1(-1.6,0) 2(1.6,0)
  silkscreen extent -0.82,-3.32 0.82,3.35, body extent -1.65,-3.25 1.65,3.25, height 0.7
05200101Z [mil] "FUSE BLOK CARTRIDGE 300V 10A PCB"
  round 80 hole 55 paste+0: 1(-475,0) 2(475,0)
  silkscreen extent -461,-201 461,201, body extent -460,-200 460,200, height 500
AssemblyNote [mil] "Assembly Note"
AssemblyNoteLabel [mil] "Assembly Note for PCB Labels"
CAPSMT_62_KE0 [mm] "12.5 x 13.5mm:  Chemi-Con KE0"
  rect 5.7x2.5 smd: 1(-4.85,0) 2(4.85,0)
  silkscreen extent -6.6,-6.6 6.6,6.6, body extent -6.6,-6.6 6.6,6.6, height 14
CONN_1-1318300-3 [mil]
  rect 100x100 hole 63: 1(-156,0) 2(0,0) 3(156,0)
CONN_1-1318300-4 [mil]
  rect 100x100 hole 63: 1(-156,0) 2(0,0) 3(156,0) 4(312,0)
CONN_22112042 [mm] "Molex"
  rect 1.65x1.65 hole 1.016 mask+0: 1(-3.81,0)
  round 1.65 hole 1.016 mask+0: 2(-1.27,0) 3(1.27,0) 4(3.81,0)
  silkscreen extent -5.08,-3.25 5.08,3.1, body extent -5.08,-3.25 5.08,3.1, height 10.68
CONN_SBH11-PBPC-D07-ST-BK [mm] "Sullins recommended land pattern"
  rect 1.65x1.65 hole 1.016 mask+0: 1(-7.62,-1.27)
  round 1.65 hole 1.016 mask+0: 2(-7.62,1.27) 3(-5.08,-1.27) 4(-5.08,1.27) 5(-2.54,-1.27) 6(-2.54,1.27) 7(0,-1.27) 8(0,1.27) 9(2.54,-1.27) 10(2.54,1.27) 11(5.08,-1.27) 12(5.08,1.27) 13(7.62,-1.27) 14(7.62,1.27)
  silkscreen extent -12.64,-5.08 12.64,4.7, body extent -12.64,-4.4 12.64,4.7, height 9.12
DBV0005A_N [mm] "SOT23, 5-Leads, Body 2.9x1.6mm, Pitch 0.95mm, Lead Span 2.8mm, IPC Medium Density"
  rect 1.1x0.65 smd: 1(-1.2,0.95) 2(-1.2,0) 3(-1.2,-0.95) 4(1.2,-0.95) 5(1.2,0.95)
  silkscreen extent -0.25,-1.55 0.25,1.55, body extent -1.42,-1.46 1.42,1.46, height 1.08
DCA_56P [mil]
  rect 58x11 smd mask+2: 1(-150.08,268.98) 2(-150.08,249.3) 3(-150.08,229.61) 4(-150.08,209.91) 5(-150.08,190.21) 6(-150.08,170.51) 7(-150.08,150.81) 8(-150.08,131.11) 9(-150.08,111.41) 10(-150.08,91.71) 11(-150.08,72.01) 12(-150.08,52.31) 13(-150.08,32.61) 14(-150.08,12.91) 15(-150.08,-6.79) 16(-150.08,-26.49) 17(-150.08,-46.19) 18(-150.08,-65.89) 19(-150.08,-85.59) 20(-150.08,-105.29) 21(-150.08,-124.99) 22(-150.08,-144.69) 23(-150.08,-164.39) 24(-150.08,-184.09) 25(-150.08,-203.79) 26(-150.08,-223.49) 27(-150.08,-243.17) 28(-150.08,-262.86) 29(149.92,-262.86) 30(149.92,-243.17) 31(149.92,-223.49) 32(149.92,-203.79) 33(149.92,-184.09) 34(149.92,-164.39) 35(149.92,-144.69) 36(149.92,-124.99) 37(149.92,-105.29) 38(149.92,-85.59) 39(149.92,-65.89) 40(149.92,-46.19) 41(149.92,-26.49) 42(149.92,-6.79) 43(149.92,12.91) 44(149.92,32.61) 45(149.92,52.31) 46(149.92,72.01) 47(149.92,91.71) 48(149.92,111.41) 49(149.92,131.11) 50(149.92,150.81) 51(149.92,170.51) 52(149.92,190.21) 53(149.92,209.91) 54(149.92,229.61) 55(149.92,249.3) 56(149.92,268.98)
  rect 141.73x251.97 smd: 57(0.02,0.01)
  silkscreen extent -247,322 -207,362
DCK0003A_N [mm] "SOT23, 3-Leads, Body 2.0x1.25mm, Pitch 0.65mm, Lead Span 2.1mm, IPC Medium Density"
  rect 1.3x0.4 smd: 1(-0.9,0.65) 2(-0.9,-0.65) 3(0.9,0)
  silkscreen extent -1.02,-1.1 0.7,1.52, body extent -0.7,-1.07 0.7,1.08, height 1.1
DCK0005A_N [mm] "SOT353, 5-Leads, Body 2x1.3mm, Pitch 0.65mm, Lead Span 2.1mm, IPC Medium Density"
  rect 0.85x0.4 smd: 1(-0.95,0.65) 2(-0.95,0) 3(-0.95,-0.65) 4(0.95,-0.65) 5(0.95,0.65)
  silkscreen extent -0.15,-1.1 0.15,1.1, body extent -1.14,-1 1.14,1, height 0.94
Diode_0603 [mm] "Based on Bourns recommended land pattern Rev 10/09"
  rect 0.7x1 smd: 1(-0.65,0) 2(0.65,0)
  silkscreen extent -1.5,-0.8 0.9,0.8, body extent -0.9,-0.5 0.9,0.5, height 0.85
DR74 [mm]
  rect 2.5x3.25 smd: 1(-3,0) 2(3,0)
  silkscreen extent -4.75,-3.8 4.75,3.8, body extent -3.8,-3.8 3.8,3.8, height 4.35
Fiducial10-20 [mm]
  round 1 smd paste-0.5 mask+0.5: 1(0,0)
  Top Layer keep-out circle w1.178: c0,0 r0.5
Keystone5010 [mil] "Keystone Multipurpose loops"
  round 87 hole 63: 1(0,0)
  silkscreen extent -70,-70 70,70, body extent -63,-63 63,62, height 319
Keystone5011 [mil] "Keystone Multipurpose loops"
  round 87 hole 63: 1(0,0)
  silkscreen extent -70,-70 70,70, body extent -63,-63 63,62, height 319
Keystone5012 [mil] "Keystone Multipurpose loops"
  round 87 hole 63: 1(0,0)
  silkscreen extent -70,-70 70,70, body extent -63,-63 63,62, height 319
Keystone5013 [mil] "Keystone Multipurpose loops"
  round 87 hole 63: 1(0,0)
  silkscreen extent -70,-70 70,70, body extent -63,-63 63,62, height 319
Keystone5014 [mil] "Keystone Multipurpose loops"
  round 87 hole 63: 1(0,0)
  silkscreen extent -70,-70 70,70, body extent -63,-63 63,62, height 319
Keystone5125 [mil] "Keystone Multipurpose loops"
  round 87 hole 63: 1(0,0)
  silkscreen extent -70,-70 70,70, body extent -63,-63 63,62, height 319
Keystone5126 [mil] "Keystone Multipurpose loops"
  round 87 hole 63: 1(0,0)
  silkscreen extent -70,-70 70,70, body extent -63,-63 63,62, height 319
Keystone5127 [mil] "Keystone Multipurpose loops"
  round 87 hole 63: 1(0,0)
  silkscreen extent -70,-70 70,70, body extent -63,-63 63,62, height 319
Keystone5128 [mil] "Keystone Multipurpose loops"
  round 87 hole 63: 1(0,0)
  silkscreen extent -70,-70 70,70, body extent -63,-63 63,62, height 319
Keystone5129 [mil] "Keystone Multipurpose loops"
  round 87 hole 63: 1(0,0)
  silkscreen extent -70,-70 70,70, body extent -63,-63 63,62, height 319
Keystone_1902C [mil] "Hex Standoff, 4-40 threaded, nylon"
  round 1 on Mech4: 0(0,0)
  body extent -145,-126 146,126, height 501
Label_650x200 [mil] "Thermal Transfer Label"
  round 1 on Mech13: 0(0,0)
  silkscreen extent -325,-100 325,100, body extent -326,-101 326,101, height 1
LED_LTST-C190 [mm] "Lite-On"
  rect 0.8x0.8 smd: 1(-0.75,0) 2(0.75,0)
  silkscreen extent -1.1,-0.8 1.8,0.8, body extent -0.85,-0.45 0.85,0.45, height 0.9
M-FLAT [mm] "Toshiba 3-4E1A recommended land pattern"
  rect 1.4x2.1 smd: 1(-2.2,0) 2(2.2,0)
  silkscreen extent -3.56,-1.47 2.77,1.47, body extent -2.45,-1.3 2.45,1.3, height 1
MF03A_N [mm] "SOT23, 3-Leads, Body 2.9x1.3mm, Pitch 0.95mm, Lead Span 2.4mm, IPC Medium Density"
  rect 1.3x0.6 smd: 1(-1.05,0.95) 2(-1.05,-0.95) 3(1.05,0)
  silkscreen extent -1.18,-1.5 0.7,1.92, body extent -0.7,-1.5 0.7,1.5, height 1.12
MOLEX_22-27-2031 [mm] "MOLEX"
  rect 1.8x1.8 hole 1.2: 1(-2.54,0)
  round 1.8 hole 1.2: 2(0,0) 3(2.54,0)
  silkscreen extent -4.37,-2.96 3.87,2.96, body extent -3.81,-2.9 3.81,2.9, height 11.72
Net-Tie_10mil [mil] "10mil net tie, no solder mask opening, no solder paste"
  rect 10x10 smd paste-5 mask-5: 1(-10,0) 2(10,0)
  Top Layer region: -6,5 6,5 6,-5 -6,-5
"NY PMS 440 0025 PH" [mm] "4-40 nylon screw and mounting hole"
  round 8 hole 3.2: 1(0,0)
  body extent -3.3,-3.3 3.3,3.3, height 2.69
OPA2365AQDRQ1 [mm] "IC OPAMP GP RRIO 50MHZ LN 8SOIC"
  rect 0.6x1.55 smd mask+0.07: 1(-1.905,-2.7) 2(-0.635,-2.7) 3(0.635,-2.7) 4(1.905,-2.7) 5(1.905,2.7) 6(0.635,2.7) 7(-0.635,2.7) 8(-1.905,2.7)
  silkscreen extent -3.05,-2.54 2.5,2, body extent -2.5,-2 2.5,2, height 1.61
PT-48 [mil]
  rect 11.81x60 smd mask+1.97: 1(-108.4,-165.9) 2(-88.7,-165.9) 3(-69,-165.9) 4(-49.3,-165.9) 5(-29.6,-165.9) 6(-9.9,-165.9) 7(9.8,-165.9) 8(29.5,-165.9) 9(49.2,-165.9) 10(68.9,-165.9) 11(88.6,-165.9) 12(108.3,-165.9) 25(108.3,166.1) 26(88.6,166.1) 27(68.9,166.1) 28(49.2,166.1) 29(29.5,166.1) 30(9.8,166.1) 31(-9.9,166.1) 32(-29.6,166.1) 33(-49.3,166.1) 34(-69,166.1) 35(-88.7,166.1) 36(-108.4,166.1)
  rect 60x11.81 smd mask+1.97: 13(166,-108.2) 14(166,-88.5) 15(166,-68.8) 16(166,-49.1) 17(166,-29.4) 18(166,-9.7) 19(166,10) 20(166,29.7) 21(166,49.4) 22(166,69.1) 23(166,88.8) 24(166,108.5) 37(-165.9,108.5) 38(-165.9,88.8) 39(-165.9,69.1) 40(-165.9,49.4) 41(-165.9,29.7) 42(-165.9,10) 43(-165.9,-9.7) 44(-165.9,-29.4) 45(-165.9,-49.1) 46(-165.9,-68.8) 47(-165.9,-88.5) 48(-165.9,-108.2)
  silkscreen extent -239,-233 -219,-213
PW0008A_N [mm] "TSOP, 8-Leads, Body 3x4.4mm, Pitch 0.65mm, IPC Medium Density"
  oval 1.7x0.35 smd: 1(-2.85,0.975) 2(-2.85,0.325) 3(-2.85,-0.325) 4(-2.85,-0.975) 5(2.85,-0.975) 6(2.85,-0.325) 7(2.85,0.325) 8(2.85,0.975)
  silkscreen extent -1.5,-1.55 1.5,1.55, body extent -3.23,-1.5 3.23,1.5, height 1.2
sod-323 [mm] "NXP recommended land pattern"
  rect 0.6x0.6 smd paste-0.05: 1(-1.1,0) 2(1.1,0)
  silkscreen extent -2.06,-0.86 1.53,0.86, body extent -1.3,-0.67 1.3,0.68, height 1.1
SRP1250-4R7MTR [mm] "INDUCTOR POWER 4.7UH 12A SMD"
  rect 4x4.5 smd paste+0: 1(-5.5,0) 2(5.5,0)
  silkscreen extent -7.05,-6.85 7.05,6.85, body extent -6.95,-6.75 6.95,6.75, height 5.9
SW_SKRKAEE010 [mm] "Alps recommended land pattern"
  rect 0.8x2 smd: 1(-2.1,0) 2(2.1,0)
  body extent -2.4,-1.45 2.4,1.45, height 1.96
TH-094MIL [mil]
  round 150 hole 94: 1(0,0)
TI_Stacked_SolderMask_Small [mil]
  rect 900x250 smd paste-125 mask-125: 0(0,0)
TRANS_NexFET_Q5A [mm] "TI recommended land pattern (nominal) M0139-01"
  rect 0.75x0.675 smd paste-0.1 mask+0.051: 1(-2.776,1.917) 2(-2.776,0.639) 3(-2.776,-0.639) 4(-2.776,-1.917)
  rect 0.655x0.675 smd paste-0.1 mask+0.051: 5(2.776,-1.917) 6(2.776,-0.639) 7(2.776,0.639) 8(2.776,1.917)
  rect 4.295x4.51 smd paste-2.2 mask+0.051: 9(0.301,0)
  silkscreen extent -3.4,-2.8 3.4,2.8, body extent -3.05,-2.5 3.05,2.5, height 1.11
XTAL_NX3225SA [mm] "NDK NX3225SA recommended land pattern"
  rect 1.4x1.2 smd: 1(-1.1,-0.8) 2(1.1,-0.8) 3(1.1,0.8) 4(-1.1,0.8)
  silkscreen extent -2.03,-1.65 2.03,1.65, body extent -1.65,-1.3 1.65,1.3, height 0.7

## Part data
C1 C3: "CAP, AL, 220uF, 50V, +/-20%, 0.23 ohm, SMD"
C2 C4 C6: "CAP, CERM, 10uF, 50V, +/-10%, X7R, 1210"
C5: "CAP, CERM, 680pF, 50V, +/-5%, C0G/NP0, 0805"
C7: "CAP, CERM, 0.01uF, 100V, +/-5%, X7R, 0603"
C8 C9 C10: "CAP, CERM, 4.7uF, 100V, +/-20%, X7R, 2220"
C11 C12 C13 C20 C21 C22: "CAP, CERM, 22pF, 50V, +/-5%, C0G/NP0, 0603"
C14 C15 C16 C23 C24 C25: "CAP, CERM, 0.047uF, 50V, +/-10%, X7R, 0603"
C17 C18 C19 C33 C38: "CAP, CERM, 0.1uF, 16V, +/-10%, X7R, 0805"
C26 C27 C30 C31 C32: "CAP, CERM, 10uF, 6.3V, +/-20%, X5R, 0603"
C28: "CAP, CERM, 2.2uF, 10V, +/-10%, X7R, 0603"
C29 C53 C56: "CAP, CERM, 1uF, 16V, +/-10%, X7R, 0603"
C34 C35: "CAP, CERM, 12pF, 50V, +/-5%, C0G/NP0, 0603"
C36 C41 C43 C47 C49 C51 C52 C54 C55 C58 C61 C63: "CAP, CERM, 0.1uF, 50V, +/-10%, X7R, 0603"
C37: library part Capacitor, "CAP CER 2200PF 50V 10% X7R 0402"
C39: "CAP, CERM, 0.01uF, 50V, +/-5%, X7R, 0805"
C40 C45: "CAP, CERM, 4.7uF, 50V, +/-10%, X7R, 1206"
C42: "CAP, CERM, 75pF, 50V, +/-5%, C0G/NP0, 0402"
C44: "CAP, CERM, 0.039uF, 10V, +/-10%, X5R, 0402"
C46: "CAP, CERM, 47uF, 10V, +/-10%, X7R, 1210"
C48 C57: "CAP, CERM, 2.2uF, 10V, +/-10%, X7R, 1206"
C50: "CAP, CERM, 0.022uF, 50V, +/-10%, X7R, 0603"
C59 C60 C62: "CAP, CERM, 0.027uF, 16V, +/-10%, X7R, 0603"
C64 C65 C66: "CAP, CERM, 1000pF, 50V, +/-10%, X7R, 0402"
D1: "Diode, Zener, 15V, 200mW, SOD-323"
D2 D3 D4 D5: "Diode, Schottky, 35V, 0.1A, 0603 Diode"
D6: "LED, Green, SMD"
D7: "Diode, Schottky, 30V, 2A, M-FLAT"
D8: "LED, Orange, SMD"
F1: "FUSE BLOK CARTRIDGE 300V 10A PCB"
FID1 FID2 FID3: "Fiducial mark.  There is nothing to buy or mount."
H1 H2 H5 H6: "Standoff, Hex, 0.5\"L #4-40 Nylon"
H3 H4 H7 H8: "Machine Screw, Round, #4-40 x 1/4, Nylon, Philips panhead"
J1 J3: "Connector, Vertical, 0.156 mil"
J2: "CONN HEADER 3POS .100 VERT TIN"
J4: "Header (shrouded), 100 mil, 7x2, Gold plated, TH"
J5: "Header, 100mil, 4x1, White, TH"
L1: library part SRP1250-4R7MTR, "INDUCTOR POWER 4.7UH 12A SMD"
L2 L4 L5 L6: "3A Ferrite Bead, 120 ohm @ 100MHz, SMD"
L3: library part BLM18SG121TN1D, "3A Ferrite Bead, 120 ohm @ 100MHz, SMD"
L7: "Inductor, Shielded Drum Core, Ferrite, 100uH, 0.86A, 0.383 ohm, SMD"
LBL1: library part THT-14-423-10, "Thermal Transfer Printable Labels, 0.650\" W x 0.200\" H - 10,000 per roll"
Logo1: library part TI_Logo, "Texas Instrument Corporate Signature"
NT1 NT2 NT3 NT4 NT5 NT6: "Single point connection between nets."
PTH-A PTH-B PTH-C: "Plated Through Hole, Dia. 0.094"
Q1 Q2 Q3 Q4 Q5 Q6 Q7: "MOSFET, N-CH, 40V, 22A, SON 5x6mm"
R1: "RES, 52.3k ohm, 1%, 0.1W, 0603"
R2 R4 R11 R12 R13: "RES, 10k ohm, 5%, 0.1W, 0603"
R3 R14 R36 R38 R41 R42 R71: "RES, 0 ohm, 5%, 0.1W, 0603"
R5 R8: "RES, 1.5k ohm, 5%, 0.1W, 0603"
R6 R52 R54 R59 R60 R61: "RES, 10k ohm, 5%, 0.063W, 0402"
R7 R10: "RES, 2.7k ohm, 5%, 0.1W, 0603"
R9: "RES, 20k ohm, 5%, 0.1W, 0603"
R15 R16 R17 R27 R28 R29: "RES, 2.21 ohm, 1%, 0.1W, 0603"
R18 R19 R20 R30 R31 R32: "RES, 1.00 ohm, 1%, 0.063W, 0402"
R21 R22 R23 R39: "RES, 34.8k ohm, 1%, 0.1W, 0603"
R24 R25 R26 R40: "RES, 4.99k ohm, 1%, 0.1W, 0603"
R33 R34 R35: "RES, 0.01 ohm, 1%, 2W, 2512 WIDE"
R37 R53: "RES, 31.6k ohm, 1%, 0.1W, 0603"
R43 R56 R69 R70: "RES, 1.0k ohm, 5%, 0.1W, 0603"
R45 R46: "RES, 2.2k ohm, 5%, 0.1W, 0603"
R47: "RES, 47k ohm, 5%, 0.063W, 0402"
R48: "RES, 300k ohm, 5%, 0.063W, 0402"
R49: "RES, 249k ohm, 1%, 0.1W, 0603"
R50: "RES, 8.87k ohm, 1%, 0.063W, 0402"
R51: "RES, 75k ohm, 5%, 0.063W, 0402"
R55 R65 R67: "RES, 10.0k ohm, 1%, 0.1W, 0603"
R58: "RES, 1.0k ohm, 5%, 0.063W, 0402"
R62 R63 R64: "RES, 56.2 ohm, 1%, 0.1W, 0603"
R66 R68: "RES, 20.0k ohm, 1%, 0.1W, 0603"
S1: "Switch, Push Button, SMD"
TP1: "Test Point, Multipurpose, Brown, TH"
TP2 TP3 TP4: "Test Point, Multipurpose, Black, TH"
TP5: "Test Point, Multipurpose, White, TH"
TP6: "Test Point, Multipurpose, Grey, TH"
TP7: "Test Point, Multipurpose, Yellow, TH"
TP8: "Test Point, Multipurpose, Green, TH"
TP9: "Test Point, Multipurpose, Red, TH"
TP10: "Test Point, Multipurpose, Orange, TH"
TP11: "Test Point, Multipurpose, Blue, TH"
TP12: "Test Point, Multipurpose, Purple, TH"
U1: "ESD Protection Array for AC Signal Data Interface, 2 Channels, -40 to +85 degC, 3-pin SC70 (DCK), Green (RoHS & no Sb/Br)"
U2: "Precision Micropower Shunt Voltage Reference, 3-pin SOT-23"
U3: library part TMS320F2802XPTA, "IC, 32-Bit Piccolo Microcontrollers, xx MHz"
U4: "Processor Supervisory Circuit, DBV0005A"
U5: "Analog Temperature Sensors with Class-AB Output, DCK0005A"
U6: "IC, 3 Phase Pre-Driver with Dual Current Shunt Amplifiers and Buck Converter"
U7: "IC OPAMP GP RRIO 50MHZ LN 8SOIC"
U8: "DUAL DIFFERENTIAL COMPARATORS, PW0008A"
Y1: library part NX3225SA-12.000000MHZ, "Crystal, 12Mhz, 8pF, SMD"
ZZ1: library part AssemblyNoteLabel
ZZ2 ZZ3 ZZ4: library part AssemblyNote

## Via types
v1: diameter 20, hole 10, Top Layer to Bottom Layer, 1027 vias

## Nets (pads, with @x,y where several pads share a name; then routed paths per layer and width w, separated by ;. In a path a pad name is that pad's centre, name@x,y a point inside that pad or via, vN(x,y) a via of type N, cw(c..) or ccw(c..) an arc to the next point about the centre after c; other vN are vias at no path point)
3P3REF: C26.1 L2.2 R36.1 | length 145
  Top Layer w10: L2.2@1530,1256.5 1533.5,1260 R36.1@1673.5,1260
